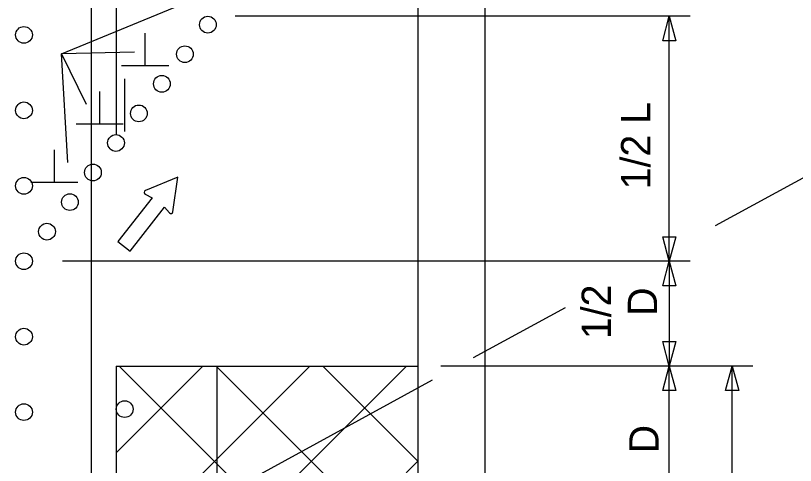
# Model space of a CAD drawing. Extents: x 16399 to 18476, y 7023 to 8321.
# Drawn here: x 17017.1 to 17203.2, y 7871.9 to 7979.3 of the extents above; entities that cross this region are included whole.
import ezdxf

# ---------------------------------------------------------------- set-up
doc = ezdxf.new("R2010")
doc.units = 0
for name, color, linetype in [('ALI_LEGAL_EX', 7, 'Continuous'), ('MT_SCRATCH_LEVEL_A', 7, 'Continuous'), ('MT_SCRATCH_LEVEL_E', 7, 'Continuous'), ('PAVT_EDGE_EX', 7, 'Continuous'), ('TRAFFIC_SIGNS_PR', 7, 'Continuous'), ('TYPICAL_TEXT_DIMEN_PR', 7, 'Continuous')]:
    doc.layers.add(name, color=color, linetype=linetype)

msp = doc.modelspace()

# ---------------------------------------------------------------- linework, layer by layer
at = {"layer": 'ALI_LEGAL_EX'}
msp.add_lwpolyline([(17043.08, 7964.14), (17043.08, 7951.59)], dxfattribs=at)
at = {"layer": 'MT_SCRATCH_LEVEL_A'}
for p, q in [((17041.08, 7895.65), (17113.08, 7895.65)), ((17041.08, 7826.39), (17110.34, 7895.65)), ((17041.08, 7874.93), (17061.8, 7895.65)), ((17113.08, 7824.39), (17041.82, 7895.65)), ((17057.78, 7866.17), (17087.26, 7895.65)), ((17113.08, 7847.48), (17064.91, 7895.65)), ((17113.08, 7872.93), (17090.36, 7895.65)), ((17041.08, 7800.93), (17113.08, 7872.93))]:
    msp.add_line(p, q, dxfattribs=at)
at = {"layer": 'MT_SCRATCH_LEVEL_E'}
for p, q in [((17055.77, 7940.7), (17048.08, 7937.5)), ((17055.77, 7940.7), (17048.08, 7937.5)), ((17054.6, 7932.43), (17055.77, 7940.7)), ((17054.6, 7932.43), (17055.77, 7940.7)), ((17048.04, 7936.67), (17049.64, 7935.82)), ((17048.04, 7936.67), (17049.64, 7935.82)), ((17049.64, 7935.82), (17041.5, 7925.36)), ((17049.64, 7935.82), (17041.5, 7925.36)), ((17044.46, 7923.06), (17052.59, 7933.53)), ((17044.46, 7923.06), (17052.59, 7933.53)), ((17052.59, 7933.53), (17053.8, 7932.19)), ((17052.59, 7933.53), (17053.8, 7932.19)), ((17041.5, 7925.36), (17044.46, 7923.06)), ((17041.5, 7925.36), (17044.46, 7923.06))]:
    msp.add_line(p, q, dxfattribs=at)
for centre, start, end in [((17048.26, 7937.07), 112.5589, 242.0978), ((17048.26, 7937.07), 112.5589, 242.0978), ((17054.14, 7932.51), 222.1702, 351.9071), ((17054.14, 7932.51), 222.1702, 351.9071)]:
    msp.add_arc(centre, 0.463, start, end, dxfattribs=at)
at = {"layer": 'PAVT_EDGE_EX'}
for p, q in [((17035.15, 8262.34), (17035.15, 7433.15)), ((17041.08, 8207.29), (17041.08, 7950.98)), ((17113.08, 8207.29), (17113.08, 7352.54)), ((17129.08, 8207.29), (17129.08, 7352.54)), ((17041.08, 7895.65), (17041.08, 7743.42)), ((17065.08, 7895.65), (17065.08, 7713.16))]:
    msp.add_line(p, q, dxfattribs=at)
at = {"layer": 'TRAFFIC_SIGNS_PR'}
for centre in [(17062.97, 7977.1), (17019.08, 7974.65), (17057.49, 7970.04), (17052, 7962.99), (17019.08, 7956.65), (17046.51, 7955.93), (17041.03, 7948.87), (17035.54, 7941.82), (17019.08, 7938.65), (17030.05, 7934.76), (17024.57, 7927.71), (17019.08, 7920.65), (17019.08, 7902.65), (17019.08, 7884.65), (17043.11, 7885.37)]:
    msp.add_circle(centre, 2, dxfattribs=at)
at = {"layer": 'TYPICAL_TEXT_DIMEN_PR'}
for p, q in [((17028.06, 7970.11), (17142.3, 8017.42)), ((17178.08, 7979.1), (17069.5, 7979.1)), ((17171.51, 7973.24), (17173.08, 7979.1)), ((17173.08, 7920.65), (17173.08, 7979.1)), ((17173.08, 7979.1), (17174.65, 7973.24)), ((17047.99, 7967.29), (17047.99, 7975.07)), ((17173.08, 7973.24), (17171.51, 7973.24)), ((17174.65, 7973.24), (17173.08, 7973.24)), ((17045.48, 7970.53), (17028.06, 7970.11)), ((17029.53, 7944.2), (17028.06, 7970.11)), ((17028.06, 7970.11), (17033.94, 7958.1)), ((17053.61, 7967.29), (17042.36, 7967.29)), ((17037.16, 7953.36), (17037.16, 7961.15)), ((17042.78, 7953.36), (17031.53, 7953.36)), ((17026.33, 7939.44), (17026.33, 7947.22)), ((17216.55, 7946.85), (17184.06, 7929.11)), ((17031.96, 7939.44), (17020.71, 7939.44)), ((17173.08, 7920.65), (17171.51, 7926.51)), ((17171.51, 7926.51), (17173.08, 7926.51)), ((17173.08, 7926.51), (17174.65, 7926.51)), ((17174.65, 7926.51), (17173.08, 7920.65)), ((17178.08, 7920.65), (17028.25, 7920.65)), ((17171.51, 7914.79), (17173.08, 7920.65)), ((17173.08, 7920.65), (17174.65, 7914.79)), ((17173.08, 7920.65), (17173.08, 7895.65)), ((17173.08, 7914.79), (17171.51, 7914.79)), ((17174.65, 7914.79), (17173.08, 7914.79)), ((17148.19, 7909.53), (17126.28, 7897.58)), ((17173.08, 7895.65), (17171.51, 7901.51)), ((17171.51, 7901.51), (17173.08, 7901.51)), ((17173.08, 7901.51), (17174.65, 7901.51)), ((17174.65, 7901.51), (17173.08, 7895.65)), ((17192.98, 7895.65), (17118.58, 7895.65)), ((17171.51, 7889.79), (17173.08, 7895.65)), ((17173.08, 7855.65), (17173.08, 7895.65)), ((17173.08, 7895.65), (17174.65, 7889.79)), ((17186.51, 7889.79), (17188.08, 7895.65)), ((17188.08, 7775.48), (17188.08, 7895.65)), ((17188.08, 7895.65), (17189.65, 7889.79)), ((17116.52, 7892.25), (17054.93, 7858.63)), ((17173.08, 7889.79), (17171.51, 7889.79)), ((17174.65, 7889.79), (17173.08, 7889.79)), ((17188.08, 7889.79), (17186.51, 7889.79)), ((17189.65, 7889.79), (17188.08, 7889.79))]:
    msp.add_line(p, q, dxfattribs=at)

# ---------------------------------------------------------------- texts
for s, p in [('1/2 L', (17168.56, 7937.81)), ('1/2', (17159.15, 7902.07)), ('D', (17170.15, 7907.64)), ('D', (17170.52, 7874.83))]:
    msp.add_text(s, height=7, rotation=90, dxfattribs=at).set_placement(p)

doc.saveas('drawing.dxf')
